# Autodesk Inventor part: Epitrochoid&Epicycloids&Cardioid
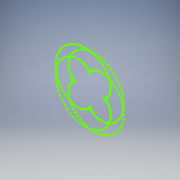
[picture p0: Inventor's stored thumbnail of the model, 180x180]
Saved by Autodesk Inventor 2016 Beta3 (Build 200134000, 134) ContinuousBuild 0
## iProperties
Created: 2008-02
Part Number: Epitrochoid&Epicycloids&Cardioid
Document SubType Name: Modeling
Designer: Autodesk, Inc.
Density: 1 g/cm^3
Material: Generic
Appearance: Default
Author: Autodesk, Inc.
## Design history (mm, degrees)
sketch "Sketch1"
  geometry: 300 further points
  constraints: 300 other
